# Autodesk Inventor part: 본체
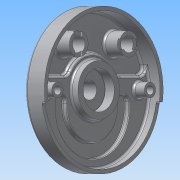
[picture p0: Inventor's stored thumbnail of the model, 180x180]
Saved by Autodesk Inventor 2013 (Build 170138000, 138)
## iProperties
Created: 2015-06
Part Number: 본체
Material: 알루미늄 6061
Document SubType Name: Modeling
Designer: Administrator
Density: 2.40731 g/cm^3
Mass: 949.174 g
Surface Area: 1033.28 cm^2
Volume: 394.288 cm^3
Author: Administrator
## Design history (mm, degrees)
sketch "스케치1"
  geometry: C1 r 95 at (0, 0); 1 further point
  constraints: 1 centre point, 1 coincident
  dimensions: "d0" = 190 diameter of C1
extrude "돌출1" new body sketch "스케치1" distance "d1" = 32; taper "d2" = 0 deg
sketch "스케치2"
  geometry: L1 (-40, 52)-(40, 52); C1 r 95 at (0, 0) reference; C2 r 10 at (-40, 52); C3 r 10 at (40, 52); A1 r 74 centre (0, 0) between (74, 0) and (-74, 0); 1 further point
  constraints: 3 centre point, 3 coincident, 2 end point, 2 horizontal alignment, 2 point on circle, 1 horizontal, 1 midpoint, 1 vertical alignment
  dimensions: "d3" = 148 diameter of A1; "d4" = 52 vertical distance of A1.start L1.end; "d5" = 80 distance of L1.end L1.start; "d6" = 20 diameter of C2; "d7" = 20 diameter of C3
extrude "돌출2" cut sketch "스케치2" distance "d8" = 32; taper "d9" = 0 deg
hole "구멍1" sketch "스케치2" diameter "d10" = 11; stored, may be unused: countersink angle "d14" = 90 deg, drill point angle "d16" = 118 deg; dims "d11" = 6, "d12" = 18, "d13" = 11, "d15" = 8
sketch "스케치4"
  geometry: C1 r 5.5 at (-74, 0) reference; C2 r 5.5 at (74, 0) reference; C3 r 10 at (40, 52) reference; C4 r 10 at (-40, 52) reference; C5 r 9 at (-74, 0); C6 r 9 at (74, 0); C7 r 15 at (40, 52); C8 r 15 at (-40, 52)
  constraints: 4 centre point, 4 coincident, 1 equal radius
  dimensions: "d17" = 30 diameter of C8; "d19" = 30 diameter of C7; "d20" = 18 diameter of C6
sketch "스케치5"
  geometry: C1 r 10 at (40, 52) reference; C2 r 10 at (-40, 52) reference; C3 r 95 at (0, 0) reference; C4 r 90 at (0, 0); C5 r 9 at (-74, 0) reference; C6 r 9 at (74, 0) reference
  constraints: 1 centre point, 1 coincident
  dimensions: "d21" = 180 diameter of C4
extrude "돌출3" cut sketch "스케치5" distance "d22" = 25; taper "d23" = 0 deg
extrude "돌출4" join sketch "스케치4" stored distance "d24" = 25; taper "d25" = 0 deg
sketch "스케치6"
  geometry: L1 (-90, 0)-(90, 0); L2 (-75.657, 16)-(-45.033, 16); L3 (45.033, 16)-(75.657, 16); C1 r 9 at (74, 0) reference; C2 r 9 at (-74, 0) reference; C3 r 90 at (0, 0) reference; C4 r 15 at (40, 52) reference; C5 r 15 at (-40, 52) reference; C6 r 9 at (74, 0) reference; C7 r 9 at (-74, 0) reference; C8 r 90 at (0, 0) reference; A1 r 90 centre (0, 0) between (88.566, 16) and (-88.566, 16) reference; A2 r 42 centre (0, 0) between (36.373, 21) and (-36.373, 21); A3 r 10 centre (45.033, 26) between (36.373, 21) and (45.033, 16); A4 r 10 centre (-45.033, 26) between (-45.033, 16) and (-36.373, 21); A5 r 90 centre (0, 0) between (85.114, 29.25) and (-85.114, 29.25); A6 r 10 centre (-75.657, 26) between (-85.114, 29.25) and (-75.657, 16); A7 r 10 centre (75.657, 26) between (75.657, 16) and (85.114, 29.25); 2 further points
  constraints: 20 point on circle, 8 tangent, 6 centre point, 6 end point, 4 point on line, 3 horizontal, 2 coincident, 2 equal radius
  dimensions: "d33" = 10 radius of A3; "d34" = 10 radius of A6
  node "투영된 루프1"
sketch "스케치7"
  geometry: C1 r 95 at (0, 0) reference; C2 r 26 at (0, 0)
  constraints: 1 centre point, 1 coincident
  dimensions: "d28" = 52 diameter of C2
extrude "돌출5" join sketch "스케치7" distance "d29" = 12; taper "d30" = -15 deg
extrude "돌출6" join sketch "스케치6" distance "d35" = 7; taper "d36" = 0 deg
sketch "스케치8"
  geometry: C1 r 35 at (0, 0); A1 r 90 centre (0, 0) between (-85.114, 29.25) and (85.114, 29.25) reference
  constraints: 1 centre point, 1 coincident
  dimensions: "d37" = 70 diameter of C1
extrude "돌출7" join sketch "스케치8" distance "d39" = 10; taper "d40" = -10 deg
sketch "스케치9"
  geometry: C1 r 33.237 at (0, 0) reference; 1 further point
  constraints: 1 coincident
hole "구멍2" sketch "스케치9" at (0, 0) diameter "d41" = 23; stored, may be unused: countersink angle "d45" = 90 deg, drill point angle "d47" = 118 deg; dims "d42" = 6, "d43" = 50, "d44" = 15, "d46" = 8
sketch "스케치10"
  geometry: L1 (0, -90)-(0, 106.968); C1 r 42 at (0, 0); A1 r 90 centre (0, 0) between (-85.114, 29.25) and (85.114, 29.25) reference; A2 r 9 centre (49.736, -14) between (58.735, -14.129) and (40.784, -14.923); A3 r 9 centre (-49.736, -14) between (-40.784, -14.923) and (-58.736, -14); A4 r 41 centre (0, -19.13) between (-40.784, -14.923) and (40.784, -14.923); A5 r 59 centre (0, -19.13) between (-58.689, -13.077) and (58.689, -13.077); 2 further points
  constraints: 12 point on circle, 5 centre point, 2 coincident, 2 end point, 2 tangent, 2 vertical alignment, 1 horizontal alignment
  dimensions: "d58" = 18 diameter of A2; "d59" = 18 diameter of A3; "d60" = 41 radius of A4; "d62" = 84 diameter of C1; "d63" = 59 radius of A5; "d99" = 14 vertical distance of A2.centre A1.centre
extrude "돌출8" cut sketch "스케치10" distance "d64" = 7; taper "d65" = 0 deg
sketch "스케치11"
  geometry: L1 (-6, -20.288)-(6, -20.288); L2 (6, -20.288)-(6, 20.288); L3 (6, 20.288)-(-6, 20.288); L4 (-6, 20.288)-(-6, -20.288); L5 (-6, -20.288)-(6, 20.288); L6 (6, -20.288)-(-6, 20.288); L7 (50.338, -6)-(109.662, -6); L8 (109.662, -6)-(109.662, 6); L9 (109.662, 6)-(50.338, 6); L10 (50.338, 6)-(50.338, -6); L11 (50.338, -6)-(109.662, 6); L12 (109.662, -6)-(50.338, 6); C1 r 15 at (0, 0) reference; C2 r 10 at (80, 0) reference; 1 further point
  constraints: 24 end point, 4 midpoint, 4 parallel, 2 horizontal, 2 perpendicular
  dimensions: "d66" = 12 distance of L2.end L3.end; "d68" = 12 distance of L7.end L8.end
extrude "돌출9" cut sketch "스케치11" distance "d69" = 3; taper "d70" = 0 deg
sketch "스케치12"
  geometry: L1 (0, 0)-(-94.075, -13.221); L2 (0, 0)-(94.075, -13.221); L3 (-95, 0)-(95, 0); L4 (68.819, 58)-(69.662, 58) reference; L5 (69.662, 58)-(69.662, 56.984) reference; C1 r 11.5 at (0, 0) reference; C2 r 95 at (0, 0) reference; A1 r 95 centre (0, 0) between (-94.075, -13.221) and (94.075, -13.221) reference; A2 r 90 centre (0, 0) between (68.819, 58) and (69.662, 56.984) reference
  constraints: 6 end point, 4 point on circle
  dimensions: "d71" = 190 distance of L3.start L3.end; "d72" = 8 deg angle of L2 L3; "d73" = 8 deg angle of L1 L3
extrude "돌출10" cut sketch "스케치12" distance "d74" = 5; taper "d75" = 0 deg
fillet "모깎기1" dims "d76" = 5
sketch "스케치13"
  geometry: C1 r 90 at (0, 0) reference; C2 r 74 at (0, 0)
  constraints: 1 centre point, 1 coincident, 1 other
  dimensions: "d77" = 148 diameter of C2
feature "엠보싱1" sketch "스케치13" dims "d78" = 0.5, "d79" = 0
fillet "모깎기2" dims "d80" = 0.3
chamfer "모따기1" distance "d81" = 1; stored, may be unused: second distance "d82" = 2, angle "d83" = 45 deg
fillet "모깎기3" dims "d84" = 3
fillet "모깎기4" dims "d86" = 3
fillet "모깎기5" dims "d87" = 3
fillet "모깎기6" dims "d88" = 3
fillet "모깎기7" dims "d89" = 3
chamfer "모따기2" distance "d90" = 1; stored, may be unused: second distance "d91" = 2, angle "d92" = 45 deg
fillet "모깎기8" dims "d96" = 1
fillet "모깎기9" dims "d97" = 3
node "솔리드1"
node "투영된 루프2"
other parameters: "d26" = 84, "d32" = 16, "d56" = 82, "d57" = 118
